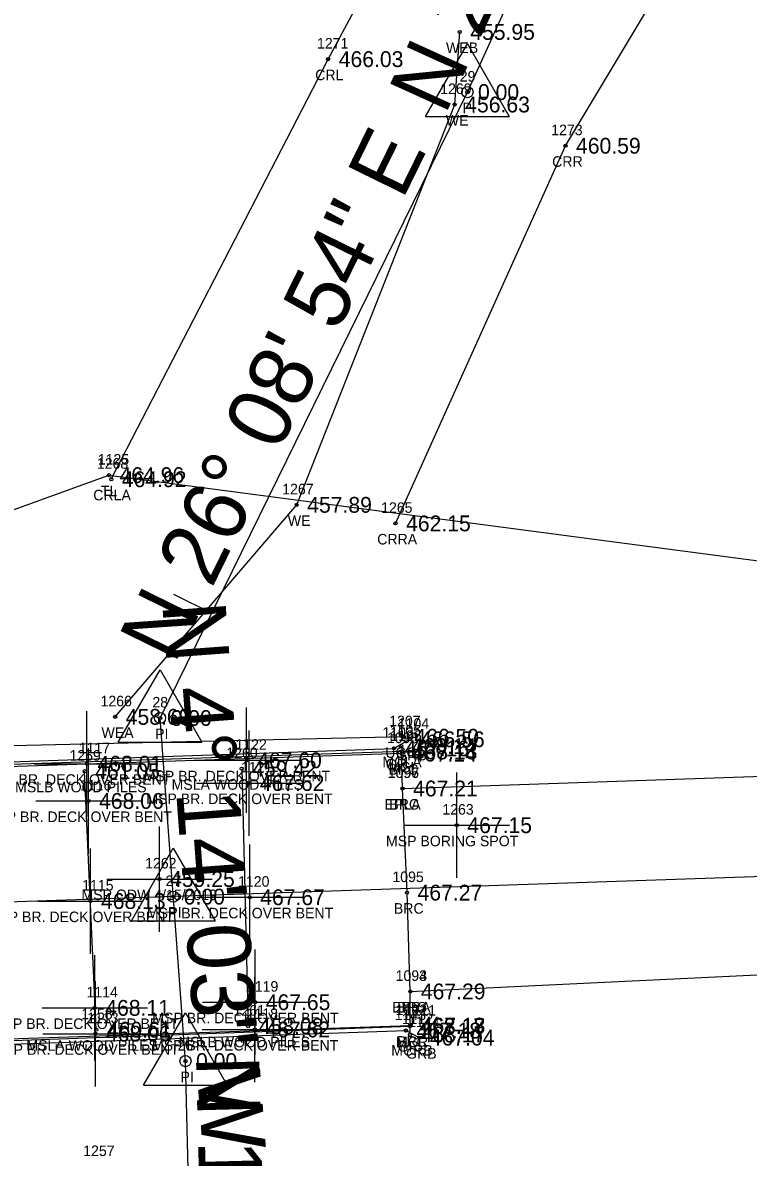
# Model space of a CAD drawing. Extents: x 1784103 to 1787401, y 770251 to 771298.
# Drawn here: x 1785788.5 to 1785857.4, y 770829.9 to 770937.5 of the extents above; entities that cross this region are included whole.
import ezdxf

# ---------------------------------------------------------------- set-up
doc = ezdxf.new("R2010")
doc.units = 0
for name, color, linetype in [('RD_EX_Bridge', 7, 'Continuous'), ('RD_EX_Bridge_txCode', 7, 'Continuous'), ('RD_EX_Conc', 7, 'Continuous'), ('RD_EX_Conc_txCode', 7, 'Continuous'), ('RD_EX_GuardRail', 7, 'Continuous'), ('RD_EX_GuardRail_txCode', 7, 'Continuous'), ('RD_EX_H2O', 7, 'Continuous'), ('RD_EX_H2O_txCode', 7, 'Continuous'), ('RD_EX_Misc', 7, 'Continuous'), ('RD_EX_Misc_txCode', 7, 'Continuous'), ('RD_EX_Road', 7, 'Continuous'), ('RD_EX_Road_txCode', 7, 'Continuous'), ('RD_EX_TX_Bridge_ELEV', 7, 'Continuous'), ('RD_EX_TX_Conc_ELEV', 7, 'Continuous'), ('RD_EX_TX_GuardRail_ELEV', 7, 'Continuous'), ('RD_EX_TX_H2O_ELEV', 7, 'Continuous'), ('RD_EX_TX_Misc_ELEV', 7, 'Continuous'), ('RD_EX_TX_Road_ELEV', 7, 'Continuous'), ('RD_EX_TX_UT_ELEV', 7, 'Continuous'), ('RD_EX_TX_VEG_ELEV', 7, 'Continuous'), ('RD_EX_UT', 7, 'Continuous'), ('RD_EX_UT_txCode', 7, 'Continuous'), ('RD_EX_VEG', 7, 'Continuous'), ('RD_EX_VEG_txCode', 7, 'Continuous'), ('RD_HC_Cl', 7, 'Continuous'), ('RD_HC_Data', 7, 'Continuous'), ('RD_HC_Data_Tic', 7, 'Continuous'), ('RD_HC_Survey_ELEV', 7, 'Continuous'), ('RD_HC_txCode', 7, 'Continuous'), ('RD_SMD_Locator', 7, 'Continuous')]:
    doc.layers.add(name, color=color, linetype=linetype)

msp = doc.modelspace()

# ---------------------------------------------------------------- linework, layer by layer
at = {"layer": 'RD_EX_Bridge'}
msp.add_lwpolyline([(1785779.71, 770863.4), (1785779.91, 770853.54), (1785780.28, 770843.87), (1785780.5, 770840.88), (1785825.3, 770842.36), (1785825.31, 770845.6), (1785825, 770854.98), (1785824.57, 770864.86), (1785824.49, 770868.17), (1785779.62, 770866.68)], dxfattribs=at)
at = {"layer": 'RD_EX_Conc'}
for points in [[(1785824.45, 770868.88), (1785824.54, 770868.38), (1785779.78, 770866.9), (1785779.66, 770867.5)], [(1785780.7, 770840.08), (1785780.59, 770840.7), (1785825.26, 770842.31), (1785825.28, 770841.51)]]:
    msp.add_lwpolyline(points, dxfattribs=at)
at = {"layer": 'RD_EX_GuardRail'}
for points in [[(1785778.91, 770868.29), (1785780.03, 770867.15), (1785823.76, 770868.67), (1785825.23, 770869.53)], [(1785779.73, 770839.55), (1785781.04, 770840.39), (1785824.89, 770841.89), (1785826.16, 770841.22)]]:
    msp.add_lwpolyline(points, dxfattribs=at)
at = {"layer": 'RD_EX_H2O'}
for p, q in [((1785801.52, 770851.27), (1785801.52, 770861.27)), ((1785796.52, 770856.27), (1785806.52, 770856.27))]:
    msp.add_line(p, q, dxfattribs=at)
for points in [[(1785796.94, 770894.21), (1785817.52, 770934.08), (1785841.28, 770978.27), (1785905.84, 771069.13), (1785934.06, 771107.4), (1785932.74, 771138.87), (1785957.1, 771183.16), (1785993.97, 771208.54), (1785990.48, 771236.16), (1786004.55, 771296.27)], [(1785823.91, 770890.02), (1785840.03, 770925.86), (1785869.79, 770975.48), (1785920.39, 771060.62), (1785947.12, 771092.26), (1785958.51, 771131.14), (1785974.06, 771169.93), (1786009.64, 771197.71), (1786027.99, 771233.04), (1786021.73, 771286.51)], [(1785797.31, 770871.66), (1785814.53, 770891.78), (1785829.52, 770929.77), (1785830, 770936.66)]]:
    msp.add_lwpolyline(points, dxfattribs=at)
msp.add_circle((1785801.52, 770856.27), 0.15, dxfattribs=at)
at = {"layer": 'RD_EX_Misc'}
for p, q in [((1785794.63, 770862.21), (1785794.63, 770872.21)), ((1785809.78, 770862.54), (1785809.78, 770872.54)), ((1785810.03, 770860.38), (1785810.03, 770870.38)), ((1785794.78, 770858.68), (1785794.78, 770868.68)), ((1785789.63, 770867.21), (1785799.63, 770867.21)), ((1785804.78, 770867.54), (1785814.78, 770867.54)), ((1785795.52, 770841.97), (1785794.41, 770866.5)), ((1785809.31, 770866.74), (1785809.93, 770842.3)), ((1785829.72, 770856.38), (1785829.72, 770866.38)), ((1785805.03, 770865.38), (1785815.03, 770865.38)), ((1785789.78, 770863.68), (1785799.78, 770863.68)), ((1785824.72, 770861.38), (1785834.72, 770861.38)), ((1785794.96, 770849.18), (1785794.96, 770859.18)), ((1785810.07, 770849.54), (1785810.07, 770859.54)), ((1785805.07, 770854.54), (1785815.07, 770854.54)), ((1785789.96, 770854.18), (1785799.96, 770854.18)), ((1785795.37, 770839.04), (1785795.37, 770849.04)), ((1785810.59, 770839.58), (1785810.59, 770849.58)), ((1785810.56, 770836.99), (1785810.56, 770846.99)), ((1785795.43, 770836.59), (1785795.43, 770846.59)), ((1785805.59, 770844.58), (1785815.59, 770844.58)), ((1785790.37, 770844.04), (1785800.37, 770844.04)), ((1785790.43, 770841.59), (1785800.43, 770841.59)), ((1785805.56, 770841.99), (1785815.56, 770841.99))]:
    msp.add_line(p, q, dxfattribs=at)
at = {"layer": 'RD_EX_Road'}
for points in [[(1785824.57, 770864.86), (1785879.1, 770866.73), (1785977.08, 770869.67), (1786078.78, 770873.52), (1786179.09, 770876.83), (1786278.08, 770880.28), (1786358.72, 770883.31), (1786381.38, 770883.94), (1786478.25, 770886.75), (1786578.04, 770889.63)], [(1785825.31, 770845.6), (1785879.29, 770848.18), (1785979.17, 770851.29), (1786079.29, 770854.66), (1786178.79, 770858.1), (1786233.56, 770860.16), (1786246.2, 770860.52), (1786278.61, 770861.3), (1786379.15, 770864.94), (1786479.01, 770868.57), (1786578.78, 770871.53)]]:
    msp.add_lwpolyline(points, dxfattribs=at)
at = {"layer": 'RD_EX_UT'}
msp.add_line((1785824.69, 770869.77), (1785780.91, 770868.76), dxfattribs=at)
at = {"layer": 'RD_EX_VEG'}
msp.add_lwpolyline([(1785221.61, 770869.17), (1785226.44, 770862.44), (1785230.83, 770863.64), (1785281.61, 770865.88), (1785330.18, 770866.95), (1785378.64, 770865.28), (1785481.03, 770871.22), (1785579.9, 770882.43), (1785678.49, 770873.66), (1785753.25, 770880.69), (1785777.57, 770887.66), (1785796.72, 770894.6), (1785878.49, 770883.8), (1786077.63, 770894.05), (1786177.75, 770898.7), (1786232.19, 770912.93), (1786276.99, 770915.77), (1786313.89, 770919.94), (1786357.9, 770947.77)], dxfattribs=at)
at = {"layer": 'RD_HC_Cl'}
for p, q in [((1785830.73, 770930.95), (1785851.44, 770976.51)), ((1785801.57, 770871.55), (1785830.73, 770930.95)), ((1787025.56, 770895.93), (1785279.14, 770836.9)), ((1785803.98, 770838.99), (1785801.57, 770871.55)), ((1785805.33, 770785.65), (1785803.98, 770838.99))]:
    msp.add_line(p, q, dxfattribs=at)
at = {"layer": 'RD_HC_Data'}
for p, q in [((1785826.76, 770928.65), (1785830.73, 770935.53)), ((1785830.73, 770935.53), (1785834.7, 770928.65)), ((1785826.76, 770928.65), (1785834.7, 770928.65)), ((1785797.6, 770869.25), (1785801.57, 770876.13)), ((1785801.57, 770876.13), (1785805.54, 770869.25)), ((1785797.6, 770869.25), (1785805.54, 770869.25)), ((1785798.85, 770852.31), (1785802.82, 770859.19)), ((1785802.82, 770859.19), (1785806.79, 770852.31)), ((1785798.85, 770852.31), (1785806.79, 770852.31)), ((1785800.01, 770836.7), (1785803.98, 770843.58)), ((1785803.98, 770843.58), (1785807.95, 770836.7)), ((1785800.01, 770836.7), (1785807.95, 770836.7))]:
    msp.add_line(p, q, dxfattribs=at)
for centre in [(1785830.73, 770930.95), (1785801.57, 770871.55), (1785802.82, 770854.6), (1785803.98, 770838.99)]:
    msp.add_circle(centre, 0.529, dxfattribs=at)
at = {"layer": 'RD_HC_Data_Tic'}
msp.add_line((1785806.46, 770881.51), (1785802.87, 770883.27), dxfattribs=at)
at = {"layer": 'RD_SMD_Locator'}
for centre in [(1785830, 770936.66), (1785817.52, 770934.08), (1785830.73, 770930.95), (1785829.52, 770929.77), (1785840.03, 770925.86), (1785796.72, 770894.6), (1785796.94, 770894.21), (1785814.53, 770891.78), (1785823.91, 770890.02), (1785797.31, 770871.66), (1785801.57, 770871.55), (1785824.69, 770869.77), (1785825.23, 770869.53), (1785823.76, 770868.67), (1785824.45, 770868.88), (1785824.49, 770868.17), (1785824.54, 770868.38), (1785794.63, 770867.21), (1785809.78, 770867.54), (1785794.41, 770866.5), (1785809.31, 770866.74), (1785810.03, 770865.38), (1785824.57, 770864.86), (1785824.57, 770864.86), (1785794.78, 770863.68), (1785829.72, 770861.38), (1785794.96, 770854.18), (1785802.82, 770854.6), (1785810.07, 770854.54), (1785825, 770854.98), (1785825.31, 770845.6), (1785825.31, 770845.6), (1785810.59, 770844.58), (1785795.37, 770844.04), (1785809.93, 770842.3), (1785825.26, 770842.31), (1785825.3, 770842.36), (1785795.43, 770841.59), (1785795.52, 770841.97), (1785810.56, 770841.99), (1785824.89, 770841.89), (1785825.28, 770841.51), (1785826.16, 770841.22), (1785803.98, 770838.99)]:
    msp.add_circle(centre, 0.15, dxfattribs=at)

# ---------------------------------------------------------------- texts
at = {"layer": 'RD_EX_Bridge_txCode'}
for s, p in [('1098', (1785823.1, 770869.17)), ('BRC', (1785823.24, 770866.17)), ('1096', (1785823.16, 770865.86)), ('BRC', (1785823.32, 770862.86)), ('1095', (1785823.61, 770855.98)), ('BRC', (1785823.75, 770852.98)), ('1093', (1785823.92, 770846.6)), ('BRC', (1785824.06, 770843.6)), ('1092', (1785823.92, 770843.36)), ('BRC', (1785824.05, 770840.36))]:
    msp.add_text(s, height=1, dxfattribs=at).set_placement(p)
at = {"layer": 'RD_EX_Conc_txCode'}
for s, p in [('1105', (1785823.35, 770869.88)), ('1106', (1785823.41, 770869.38)), ('MCLA', (1785822.67, 770866.88)), ('MCL', (1785823.24, 770866.38)), ('1112', (1785824.5, 770842.51)), ('1111', (1785824.77, 770843.31)), ('MCRB', (1785823.5, 770839.51)), ('MCR', (1785823.95, 770840.31))]:
    msp.add_text(s, height=1, dxfattribs=at).set_placement(p)
at = {"layer": 'RD_EX_GuardRail_txCode'}
for s, p in [('1104', (1785824.12, 770870.53)), ('1103', (1785822.66, 770869.67)), ('GRB', (1785823.97, 770867.53)), ('GR', (1785822.98, 770866.67)), ('1143', (1785823.83, 770842.89)), ('1144', (1785825.1, 770842.22)), ('GR', (1785824.11, 770839.89)), ('GRB', (1785824.91, 770839.22))]:
    msp.add_text(s, height=1, dxfattribs=at).set_placement(p)
at = {"layer": 'RD_EX_H2O_txCode'}
for s, p in [('1271', (1785816.46, 770935.08)), ('WEB', (1785828.7, 770934.66)), ('CRL', (1785816.29, 770932.08)), ('1269', (1785828.15, 770930.77)), ('WE', (1785828.68, 770927.77)), ('1273', (1785838.68, 770926.86)), ('CRR', (1785838.77, 770923.86)), ('1268', (1785795.57, 770895.21)), ('CRLA', (1785795.23, 770892.21)), ('1267', (1785813.16, 770892.78)), ('1265', (1785822.54, 770891.02)), ('WE', (1785813.69, 770889.78)), ('CRRA', (1785822.17, 770888.02)), ('1266', (1785795.92, 770872.66)), ('WEA', (1785796.01, 770869.66)), ('1262', (1785800.15, 770857.27)), ('MSP ODW 4/15/2019', (1785794.11, 770854.27)), ('1257', (1785794.28, 770829.98))]:
    msp.add_text(s, height=1, dxfattribs=at).set_placement(p)
at = {"layer": 'RD_EX_Misc_txCode'}
for s, p in [('1122', (1785808.72, 770868.54)), ('1259', (1785792.97, 770867.5)), ('1117', (1785793.85, 770868.21)), ('1260', (1785807.85, 770867.74)), ('1121', (1785809.25, 770866.38)), ('MSP BR. DECK OVER BENT', (1785784.87, 770865.21)), ('MSP BR. DECK OVER BENT', (1785800.02, 770865.54)), ('MSLB WOOD PILES', (1785787.81, 770864.5)), ('1116', (1785793.97, 770864.68)), ('MSLA WOOD PILES', (1785802.66, 770864.74)), ('MSP BR. DECK OVER BENT', (1785800.26, 770863.38)), ('1263', (1785828.35, 770862.38)), ('MSP BR. DECK OVER BENT', (1785785.01, 770861.68)), ('MSP BORING SPOT', (1785823, 770859.38)), ('1120', (1785808.97, 770855.54)), ('1115', (1785794.18, 770855.18)), ('MSP BR. DECK OVER BENT', (1785785.2, 770852.18)), ('MSP BR. DECK OVER BENT', (1785800.31, 770852.54)), ('1114', (1785794.59, 770845.04)), ('1119', (1785809.81, 770845.58)), ('1258', (1785794.09, 770842.97)), ('1113', (1785794.65, 770842.59)), ('MSP BR. DECK OVER BENT', (1785800.83, 770842.58)), ('1261', (1785808.54, 770843.3)), ('1118', (1785809.78, 770842.99)), ('MSP BR. DECK OVER BENT', (1785785.6, 770842.04)), ('MSP BR. DECK OVER BENT', (1785785.67, 770839.59)), ('MSLA WOOD PILES', (1785788.88, 770839.97)), ('MSP BR. DECK OVER BENT', (1785800.8, 770839.99)), ('MSLB WOOD PILES', (1785803.32, 770840.3))]:
    msp.add_text(s, height=1, dxfattribs=at).set_placement(p)
at = {"layer": 'RD_EX_Road_txCode'}
for s, p in [('1097', (1785823.18, 770865.86)), ('EPLA', (1785822.87, 770862.86)), ('1094', (1785823.92, 770846.6)), ('EPRA', (1785823.59, 770843.6))]:
    msp.add_text(s, height=1, dxfattribs=at).set_placement(p)
at = {"layer": 'RD_EX_TX_Bridge_ELEV'}
for s, p in [('467.14', (1785825.49, 770867.42)), ('467.21', (1785825.57, 770864.11)), ('467.27', (1785826, 770854.23)), ('467.29', (1785826.31, 770844.85)), ('467.18', (1785826.3, 770841.61))]:
    msp.add_text(s, height=1.5, dxfattribs=at).set_placement(p)
at = {"layer": 'RD_EX_TX_Conc_ELEV'}
for s, p in [('468.14', (1785825.45, 770868.13)), ('468.13', (1785825.54, 770867.63)), ('468.17', (1785826.26, 770841.56)), ('468.17', (1785826.28, 770840.76))]:
    msp.add_text(s, height=1.5, dxfattribs=at).set_placement(p)
at = {"layer": 'RD_EX_TX_GuardRail_ELEV'}
for s, p in [('467.16', (1785824.76, 770867.92)), ('466.56', (1785826.23, 770868.78)), ('467.18', (1785825.89, 770841.14)), ('467.04', (1785827.16, 770840.47))]:
    msp.add_text(s, height=1.5, dxfattribs=at).set_placement(p)
at = {"layer": 'RD_EX_TX_H2O_ELEV'}
for s, p in [('455.95', (1785831, 770935.91)), ('466.03', (1785818.52, 770933.33)), ('456.63', (1785830.52, 770929.02)), ('460.59', (1785841.03, 770925.11)), ('464.92', (1785797.94, 770893.46)), ('457.89', (1785815.53, 770891.03)), ('462.15', (1785824.91, 770889.27)), ('458.69', (1785798.31, 770870.91)), ('459.25', (1785802.52, 770855.52))]:
    msp.add_text(s, height=1.5, dxfattribs=at).set_placement(p)
at = {"layer": 'RD_EX_TX_Misc_ELEV'}
for s, p in [('467.60', (1785810.78, 770866.79)), ('461.05', (1785795.41, 770865.75)), ('468.01', (1785795.63, 770866.46)), ('459.42', (1785810.31, 770865.99)), ('467.62', (1785811.03, 770864.63)), ('468.06', (1785795.78, 770862.93)), ('467.15', (1785830.72, 770860.63)), ('468.13', (1785795.96, 770853.43)), ('467.67', (1785811.07, 770853.79)), ('468.11', (1785796.37, 770843.29)), ('467.65', (1785811.59, 770843.83)), ('460.61', (1785796.52, 770841.22)), ('458.08', (1785810.93, 770841.55)), ('467.62', (1785811.56, 770841.24)), ('468.06', (1785796.43, 770840.84))]:
    msp.add_text(s, height=1.5, dxfattribs=at).set_placement(p)
at = {"layer": 'RD_EX_TX_Road_ELEV'}
for s, p in [('467.21', (1785825.57, 770864.11)), ('467.29', (1785826.31, 770844.85))]:
    msp.add_text(s, height=1.5, dxfattribs=at).set_placement(p)
at = {"layer": 'RD_EX_TX_UT_ELEV'}
msp.add_text('466.50', height=1.5, dxfattribs=at).set_placement((1785825.69, 770869.02))
at = {"layer": 'RD_EX_TX_VEG_ELEV'}
msp.add_text('464.96', height=1.5, dxfattribs=at).set_placement((1785797.72, 770893.85))
at = {"layer": 'RD_EX_UT_txCode'}
for s, p in [('1207', (1785823.31, 770870.77)), ('UGCA', (1785822.94, 770867.77))]:
    msp.add_text(s, height=1, dxfattribs=at).set_placement(p)
at = {"layer": 'RD_EX_VEG_txCode'}
for s, p in [('1125', (1785795.66, 770895.6)), ('TL', (1785795.95, 770892.6))]:
    msp.add_text(s, height=1, dxfattribs=at).set_placement(p)
at = {"layer": 'RD_HC_Data'}
for s, rotation, p in [('N 24%%d 26\' 49" E', 65.553, (1785828.6, 770928.67)), ('N 26%%d 08\' 54" E', 63.8516, (1785802.92, 770876.57)), ('N 4%%d 14\' 03" W', 274.2342, (1785801.77, 770882.39)), ('N 1%%d 27\' 00" W', 271.45, (1785804.97, 770839.46))]:
    msp.add_text(s, height=6, rotation=rotation, dxfattribs=at).set_placement(p)
at = {"layer": 'RD_HC_Survey_ELEV'}
for p in [(1785831.73, 770930.2), (1785802.57, 770870.8), (1785803.82, 770853.85), (1785804.98, 770838.24)]:
    msp.add_text('0.00', height=1.5, dxfattribs=at).set_placement(p)
at = {"layer": 'RD_HC_txCode'}
for s, p in [('29', (1785830, 770931.95)), ('PI', (1785830.26, 770928.95)), ('28', (1785800.84, 770872.55)), ('PI', (1785801.1, 770869.55)), ('27', (1785802.09, 770855.6)), ('PI', (1785802.35, 770852.6)), ('26', (1785803.22, 770839.99)), ('PI', (1785803.51, 770836.99))]:
    msp.add_text(s, height=1, dxfattribs=at).set_placement(p)

doc.saveas('drawing.dxf')
